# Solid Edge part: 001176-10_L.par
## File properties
Last saved by: morva
Revision: 82
Accuracy: 0.990
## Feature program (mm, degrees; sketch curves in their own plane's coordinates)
body "unnamed Body 1"
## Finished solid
Body 1: solid body, 32 faces, 67 edges, 38 vertices.
  Faces by surface: cone 11, torus 10, plane 9, cylinder 2
  Edges by curve: circle 39, line 19, curve on surface 6, spline 3
Bounding box of the edges (mm; curved faces can reach further): 14.049 x 22.464 x 9.628, from (504.3967, 412.602, -102.77) to (518.4459, 435.0662, -93.1422).
Cylindrical faces by radius (mm): R2.5 x2
Conical faces (half-angle, radius in mm at the cone's reference point): 45 deg R2.3094 x7, 45 deg R2.5 x2, 45 deg R4.4561 x2
Toroidal faces (ring radius, tube radius in mm): R0.6241 r3.9478 x2, R2.7 r0.2 x2, R3.5613 r1 x4, R4.3147 r0.2 x2
Planar faces by outward normal: oblique 9
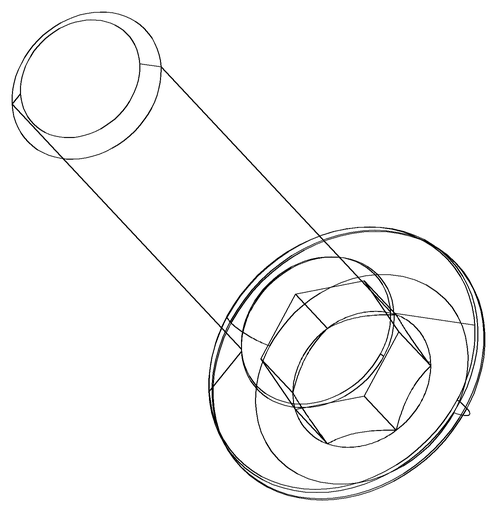
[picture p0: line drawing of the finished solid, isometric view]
